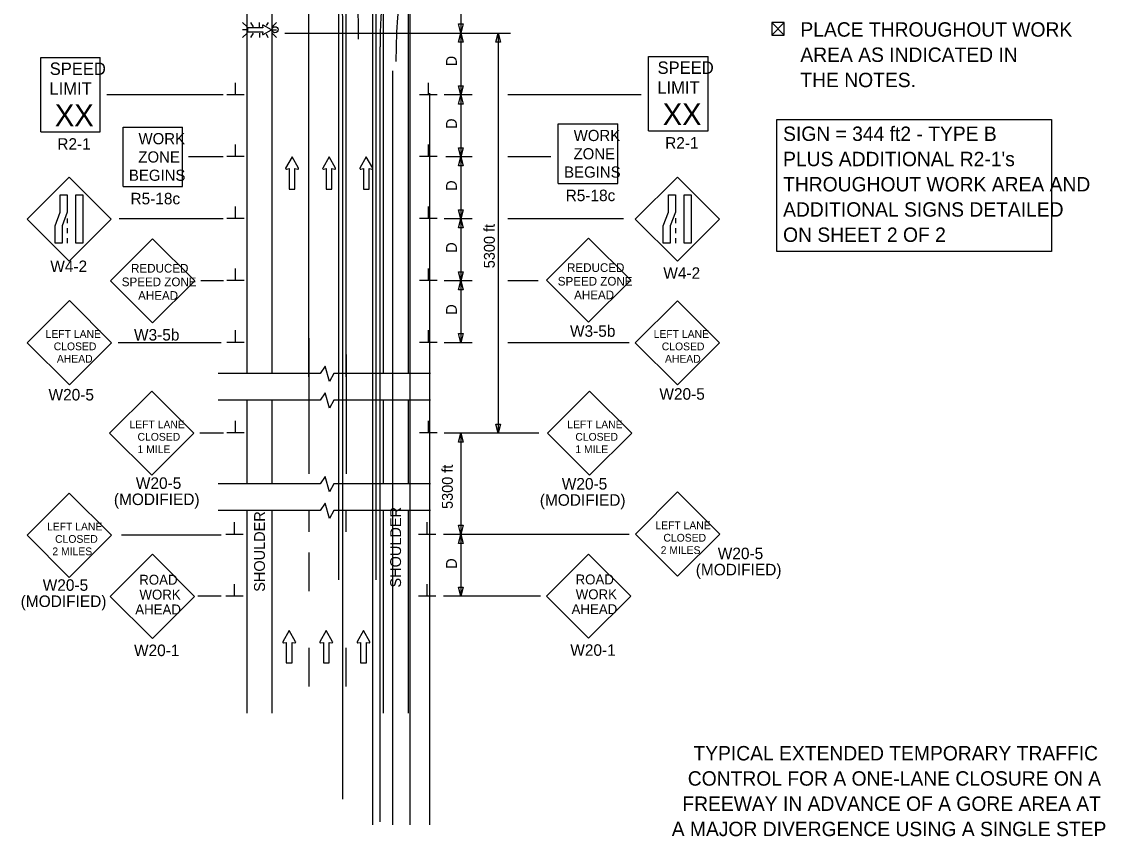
# Model space of a CAD drawing. Extents: x 16284 to 18468, y 5417 to 6974.
# Drawn here: x 16740 to 17439, y 5990 to 6516 of the extents above; entities that cross this region are included whole.
import ezdxf

# ---------------------------------------------------------------- set-up
doc = ezdxf.new("R2010")
doc.units = 0
for name, color, linetype in [('ALI_LEGAL_EX', 7, 'Continuous'), ('BORDER', 7, 'Continuous'), ('MT_SCRATCH_LEVEL_E', 7, 'Continuous'), ('PAVT_EDGE_EX', 7, 'Continuous'), ('TRAFFIC_SIGNS_PR', 7, 'Continuous'), ('TYPICAL_TEXT_DIMEN_EX', 7, 'Continuous'), ('TYPICAL_TEXT_DIMEN_PR', 7, 'Continuous')]:
    doc.layers.add(name, color=color, linetype=linetype)

msp = doc.modelspace()

# ---------------------------------------------------------------- linework, layer by layer
at = {"layer": 'ALI_LEGAL_EX'}
for p, q in [((16944.3, 6974.12), (16944.3, 6155.98)), ((16968.3, 6974.12), (16968.3, 6155.98)), ((16966.29, 6836.53), (16966.29, 5997.6)), ((16990.29, 6836.53), (16990.29, 5997.6)), ((16925.13, 6287.02), (16925.13, 6564.7)), ((16949.13, 6287.02), (16949.13, 6564.7)), ((16947.12, 6014.17), (16947.12, 6514.52)), ((16971.12, 5999.68), (16971.12, 6500.03)), ((16979.26, 5997.6), (16979.26, 6484.64)), ((17003.26, 5997.6), (17003.26, 6470.15)), ((16925.13, 6301.47), (16925.13, 6224.31)), ((16949.13, 6301.47), (16949.13, 6224.31))]:
    msp.add_line(p, q, dxfattribs=at)
for points in [[(16925.13, 6487.02), (16925.13, 6509.03)], [(16949.13, 6487.02), (16949.13, 6509.03)], [(16925.13, 6387.02), (16925.13, 6412.02)], [(16949.13, 6387.02), (16949.13, 6412.02)], [(16925.13, 6312.02), (16925.13, 6287.02)], [(16925.13, 6312.02), (16925.13, 6289.11)], [(16949.13, 6289.11), (16949.13, 6312.02)], [(16925.13, 6273.62), (16925.13, 6248.62)], [(16925.13, 6200.69), (16925.13, 6187.02)], [(16949.13, 6187.02), (16949.13, 6200.69)], [(16925.13, 6173.62), (16925.13, 6148.62)], [(16925.13, 6112.02), (16925.13, 6087.02)], [(16949.13, 6087.02), (16949.13, 6112.02)]]:
    msp.add_lwpolyline(points, dxfattribs=at)
for centre, radius, start, end in [((16583.12, 6514.52), 364, 0, 57.29578), ((16593.27, 6505.1), 364, 0, 57.29578), ((17311.12, 6500.03), 340, 129.56655, 180), ((17321.27, 6490.61), 340, 129.56655, 180)]:
    msp.add_arc(centre, radius, start, end, dxfattribs=at)
at = {"layer": 'MT_SCRATCH_LEVEL_E'}
for p, q in [((16914.27, 6429.09), (16910.15, 6421.85)), ((16918.41, 6421.85), (16914.27, 6429.09)), ((16938.17, 6429.09), (16934.06, 6421.85)), ((16942.32, 6421.85), (16938.17, 6429.09)), ((16962.22, 6429.09), (16958.11, 6421.85)), ((16966.37, 6421.85), (16962.22, 6429.09)), ((16910.64, 6421.16), (16912.41, 6421.48)), ((16912.41, 6421.48), (16912.41, 6408.22)), ((16916.16, 6408.22), (16916.16, 6421.48)), ((16916.16, 6421.48), (16917.93, 6421.16)), ((16934.54, 6421.16), (16936.32, 6421.48)), ((16936.32, 6421.48), (16936.32, 6408.22)), ((16940.06, 6408.22), (16940.06, 6421.48)), ((16940.06, 6421.48), (16941.84, 6421.16)), ((16958.59, 6421.16), (16960.37, 6421.48)), ((16960.37, 6421.48), (16960.37, 6408.22)), ((16964.11, 6408.22), (16964.11, 6421.48)), ((16964.11, 6421.48), (16965.89, 6421.16)), ((16912.41, 6408.22), (16916.16, 6408.22)), ((16936.32, 6408.22), (16940.06, 6408.22)), ((16960.37, 6408.22), (16964.11, 6408.22)), ((16912.44, 6123.16), (16908.32, 6115.92)), ((16916.58, 6115.92), (16912.44, 6123.16)), ((16936.34, 6123.16), (16932.23, 6115.92)), ((16940.49, 6115.92), (16936.34, 6123.16)), ((16960.39, 6123.16), (16956.28, 6115.92)), ((16964.54, 6115.92), (16960.39, 6123.16)), ((16908.81, 6115.24), (16910.58, 6115.55)), ((16910.58, 6115.55), (16910.58, 6102.29)), ((16914.33, 6102.29), (16914.33, 6115.55)), ((16914.33, 6115.55), (16916.1, 6115.24)), ((16932.71, 6115.24), (16934.49, 6115.55)), ((16934.49, 6115.55), (16934.49, 6102.29)), ((16938.23, 6102.29), (16938.23, 6115.55)), ((16938.23, 6115.55), (16940.01, 6115.24)), ((16956.76, 6115.24), (16958.54, 6115.55)), ((16958.54, 6115.55), (16958.54, 6102.29)), ((16962.28, 6102.29), (16962.28, 6115.55)), ((16962.28, 6115.55), (16964.06, 6115.24)), ((16910.58, 6102.29), (16914.33, 6102.29)), ((16934.49, 6102.29), (16938.23, 6102.29)), ((16958.54, 6102.29), (16962.28, 6102.29))]:
    msp.add_line(p, q, dxfattribs=at)
for centre, start, end in [((16910.56, 6421.62), 150.42484, 279.96381), ((16918, 6421.62), 260.03619, 29.77312), ((16934.47, 6421.62), 150.42484, 279.96381), ((16941.91, 6421.62), 260.03619, 29.77312), ((16958.52, 6421.62), 150.42484, 279.96381), ((16965.96, 6421.62), 260.03619, 29.77312), ((16908.73, 6115.69), 150.42484, 279.96381), ((16916.17, 6115.7), 260.03619, 29.77312), ((16932.64, 6115.69), 150.42484, 279.96381), ((16940.08, 6115.7), 260.03619, 29.77312), ((16956.69, 6115.69), 150.42484, 279.96381), ((16964.13, 6115.7), 260.03619, 29.77312)]:
    msp.add_arc(centre, 0.463, start, end, dxfattribs=at)
at = {"layer": 'PAVT_EDGE_EX'}
for p, q in [((16885.13, 6564.7), (16885.13, 6289.11)), ((16901.13, 6564.7), (16901.13, 6289.11)), ((16973.13, 6564.7), (16973.13, 6289.11)), ((16989.13, 6564.7), (16989.13, 6289.11)), ((16885.13, 6271.97), (16885.13, 6217.82)), ((16901.13, 6271.97), (16901.13, 6217.82)), ((16973.13, 6271.97), (16973.13, 6217.82)), ((16989.13, 6271.97), (16989.13, 6217.82)), ((16885.13, 6200.69), (16885.13, 6069.75)), ((16901.13, 6200.69), (16901.13, 6069.75)), ((16973.13, 6200.69), (16973.13, 6069.75)), ((16989.13, 6200.69), (16989.13, 6069.75))]:
    msp.add_line(p, q, dxfattribs=at)
at = {"layer": 'TRAFFIC_SIGNS_PR'}
for p, q in [((16885.2, 6513.11), (16882.38, 6515.93)), ((16887.5, 6515.93), (16889.13, 6513.11)), ((16893.29, 6513.11), (16893.29, 6515.93)), ((16898.76, 6515.93), (16897.55, 6513.83)), ((16904.19, 6515.92), (16901.37, 6513.11)), ((16885.2, 6511.07), (16882.38, 6511.07)), ((16885.2, 6509.04), (16882.38, 6506.22)), ((16889.15, 6509.04), (16887.52, 6506.22)), ((16893.29, 6509.04), (16893.29, 6506.22)), ((16897.47, 6508.41), (16898.73, 6506.22)), ((16901.37, 6511.07), (16904.19, 6511.07)), ((16904.19, 6506.22), (16901.37, 6509.04)), ((16752.07, 6493.12), (16790.47, 6493.12)), ((16752.07, 6445.12), (16752.07, 6493.12)), ((16790.47, 6445.12), (16790.47, 6493.12)), ((17144.45, 6493.8), (17182.85, 6493.8)), ((17144.45, 6445.8), (17144.45, 6493.8)), ((17182.85, 6445.8), (17182.85, 6493.8)), ((17086.09, 6411.89), (17086.09, 6450.29)), ((17086.09, 6450.29), (17124.49, 6450.29)), ((17124.49, 6411.89), (17124.49, 6450.29)), ((16752.07, 6445.12), (16790.47, 6445.12)), ((16805.17, 6409.84), (16805.17, 6448.24)), ((16805.17, 6448.24), (16843.57, 6448.24)), ((16843.57, 6409.84), (16843.57, 6448.24)), ((17144.45, 6445.8), (17182.85, 6445.8)), ((16770.39, 6416.02), (16743.23, 6388.86)), ((16797.54, 6388.86), (16770.39, 6416.02)), ((17163, 6416.04), (17135.85, 6388.89)), ((17190.15, 6388.89), (17163, 6416.04)), ((16805.17, 6409.84), (16843.57, 6409.84)), ((17086.09, 6411.89), (17124.49, 6411.89)), ((16743.23, 6388.86), (16770.39, 6361.71)), ((16769.14, 6389.36), (16769.14, 6386.16)), ((16770.39, 6361.71), (16797.54, 6388.86)), ((17135.85, 6388.89), (17163, 6361.73)), ((17161.75, 6389.38), (17161.75, 6386.18)), ((17163, 6361.73), (17190.15, 6388.89)), ((16769.14, 6382.96), (16769.14, 6379.76)), ((17161.75, 6382.98), (17161.75, 6379.78)), ((16769.14, 6376.56), (16769.14, 6373.36)), ((16824.3, 6376.18), (16797.15, 6349.03)), ((16851.45, 6349.03), (16824.3, 6376.18)), ((17105.74, 6376.58), (17078.59, 6349.43)), ((17132.9, 6349.43), (17105.74, 6376.58)), ((17161.75, 6376.58), (17161.75, 6373.38)), ((16797.15, 6349.03), (16824.3, 6321.88)), ((16824.3, 6321.88), (16851.45, 6349.03)), ((17078.59, 6349.43), (17105.74, 6322.27)), ((17105.74, 6322.27), (17132.9, 6349.43)), ((16770.51, 6336.22), (16743.32, 6309.03)), ((16797.7, 6309.03), (16770.51, 6336.22)), ((17163.03, 6336.19), (17135.84, 6309)), ((17190.22, 6309), (17163.03, 6336.19)), ((16743.32, 6309.03), (16770.51, 6281.85)), ((16770.51, 6281.85), (16797.7, 6309.03)), ((17135.84, 6309), (17163.03, 6281.81)), ((17163.03, 6281.81), (17190.22, 6309)), ((16823.71, 6277.82), (16796.52, 6250.64)), ((16850.9, 6250.64), (16823.71, 6277.82)), ((17106.33, 6277.81), (17079.14, 6250.62)), ((17133.51, 6250.62), (17106.33, 6277.81)), ((16796.52, 6250.64), (16823.71, 6223.45)), ((16823.71, 6223.45), (16850.9, 6250.64)), ((17079.14, 6250.62), (17106.33, 6223.43)), ((17106.33, 6223.43), (17133.51, 6250.62)), ((16770.49, 6211.86), (16743.31, 6184.67)), ((16797.68, 6184.67), (16770.49, 6211.86)), ((17163.18, 6212.64), (17136, 6185.45)), ((17190.37, 6185.45), (17163.18, 6212.64)), ((16743.31, 6184.67), (16770.49, 6157.49)), ((16770.49, 6157.49), (16797.68, 6184.67)), ((17136, 6185.45), (17163.18, 6158.27)), ((17163.18, 6158.27), (17190.37, 6185.45)), ((16824.1, 6172.41), (16796.94, 6145.26)), ((16851.25, 6145.26), (16824.1, 6172.41)), ((17105.74, 6172.59), (17078.59, 6145.44)), ((17132.9, 6145.44), (17105.74, 6172.59)), ((16796.94, 6145.26), (16824.1, 6118.11)), ((16824.1, 6118.11), (16851.25, 6145.26)), ((17078.59, 6145.44), (17105.74, 6118.28)), ((17105.74, 6118.28), (17132.9, 6145.44))]:
    msp.add_line(p, q, dxfattribs=at)
for points in [[(16895.11, 6513.76), (16895.34, 6512.46), (16885.62, 6512.46), (16885.62, 6509.72), (16895.34, 6509.72), (16895.11, 6508.41)], [(16895.61, 6508.06), (16900.92, 6511.07), (16895.61, 6514.11)]]:
    msp.add_lwpolyline(points, dxfattribs=at)
for points in [[(16769.14, 6404.6), (16769.14, 6393.42), (16765.8, 6384.54), (16765.8, 6373.36), (16761.3, 6373.36), (16761.3, 6384.54), (16764.65, 6393.42), (16764.65, 6404.6)], [(16779.28, 6404.6), (16779.28, 6373.36), (16774.78, 6373.36), (16774.78, 6404.6)], [(17161.75, 6404.62), (17161.75, 6393.44), (17158.41, 6384.56), (17158.41, 6373.38), (17153.91, 6373.38), (17153.91, 6384.56), (17157.26, 6393.44), (17157.26, 6404.62)], [(17171.89, 6404.62), (17171.89, 6373.38), (17167.4, 6373.38), (17167.4, 6404.62)]]:
    msp.add_lwpolyline(points, close=True, dxfattribs=at)
msp.add_circle((16903.24, 6511.12), 2, dxfattribs=at)
for centre, start, end in [((16895.45, 6513.81), 61.48329, 189.95933), ((16895.45, 6508.36), 170.73078, 298.89165)]:
    msp.add_arc(centre, 0.341, start, end, dxfattribs=at)
at = {"layer": 'TYPICAL_TEXT_DIMEN_EX'}
msp.add_lwpolyline([(17227.21, 6453.17), (17404.48, 6453.17), (17404.48, 6367.85), (17227.21, 6367.85)], close=True, dxfattribs=at)
at = {"layer": 'TYPICAL_TEXT_DIMEN_PR'}
for p, q in [((17023.24, 6541.14), (17023.24, 6509.03)), ((17023.24, 6509.03), (17021.67, 6514.9)), ((17021.67, 6514.9), (17023.24, 6514.9)), ((17023.24, 6514.9), (17024.81, 6514.9)), ((17024.81, 6514.9), (17023.24, 6509.03)), ((17224.01, 6515.74), (17232.01, 6507.74)), ((17224.01, 6507.74), (17232.01, 6515.74)), ((16909.53, 6509.03), (17055.35, 6509.03)), ((17021.67, 6503.17), (17023.24, 6509.03)), ((17023.24, 6509.03), (17023.24, 6469.03)), ((17023.24, 6509.03), (17024.81, 6503.17)), ((17045.77, 6503.17), (17047.34, 6509.03)), ((17047.34, 6509.03), (17047.34, 6250.63)), ((17047.34, 6509.03), (17048.91, 6503.17)), ((17023.24, 6503.17), (17021.67, 6503.17)), ((17024.81, 6503.17), (17023.24, 6503.17)), ((17047.34, 6503.17), (17045.77, 6503.17)), ((17048.91, 6503.17), (17047.34, 6503.17)), ((16877.81, 6469.12), (16877.81, 6476.9)), ((17002.26, 6469.12), (17002.26, 6476.9)), ((17023.24, 6469.03), (17021.67, 6474.9)), ((17021.67, 6474.9), (17023.24, 6474.9)), ((17023.24, 6474.9), (17024.81, 6474.9)), ((17024.81, 6474.9), (17023.24, 6469.03)), ((16869.89, 6469.03), (16794.8, 6469.03)), ((16883.43, 6469.12), (16872.18, 6469.12)), ((17007.88, 6469.12), (16996.63, 6469.12)), ((17030.45, 6469.03), (17012.41, 6469.03)), ((17021.67, 6463.17), (17023.24, 6469.03)), ((17023.24, 6469.03), (17023.24, 6429.03)), ((17023.24, 6469.03), (17024.81, 6463.17)), ((17139.57, 6469.03), (17053.57, 6469.03)), ((17023.24, 6463.17), (17021.67, 6463.17)), ((17024.81, 6463.17), (17023.24, 6463.17)), ((16877.69, 6429.28), (16877.69, 6437.06)), ((17002.26, 6429.28), (17002.26, 6437.06)), ((16869.89, 6429.03), (16847.44, 6429.03)), ((16883.32, 6429.28), (16872.07, 6429.28)), ((17007.88, 6429.28), (16996.63, 6429.28)), ((17030.45, 6429.03), (17013.53, 6429.03)), ((17023.24, 6429.03), (17021.67, 6434.9)), ((17021.67, 6434.9), (17023.24, 6434.9)), ((17021.67, 6423.17), (17023.24, 6429.03)), ((17023.24, 6434.9), (17024.81, 6434.9)), ((17024.81, 6434.9), (17023.24, 6429.03)), ((17023.24, 6429.03), (17023.24, 6389.03)), ((17023.24, 6429.03), (17024.81, 6423.17)), ((17081.26, 6429.03), (17053.57, 6429.03)), ((17023.24, 6423.17), (17021.67, 6423.17)), ((17024.81, 6423.17), (17023.24, 6423.17)), ((16877.69, 6389.28), (16877.69, 6397.06)), ((17002.26, 6389.28), (17002.26, 6397.06)), ((17023.24, 6389.03), (17021.67, 6394.9)), ((17021.67, 6394.9), (17023.24, 6394.9)), ((17023.24, 6394.9), (17024.81, 6394.9)), ((17024.81, 6394.9), (17023.24, 6389.03)), ((16869.89, 6389.03), (16802.62, 6389.03)), ((16883.32, 6389.28), (16872.07, 6389.28)), ((17007.88, 6389.28), (16996.63, 6389.28)), ((17030.45, 6389.03), (17012.41, 6389.03)), ((17021.67, 6383.17), (17023.24, 6389.03)), ((17023.24, 6389.03), (17023.24, 6349.03)), ((17023.24, 6389.03), (17024.81, 6383.17)), ((17128.19, 6389.03), (17053.57, 6389.03)), ((17023.24, 6383.17), (17021.67, 6383.17)), ((17024.81, 6383.17), (17023.24, 6383.17)), ((16877.69, 6349.28), (16877.69, 6357.06)), ((17002.26, 6349.28), (17002.26, 6357.06)), ((17023.24, 6349.03), (17021.67, 6354.9)), ((17021.67, 6354.9), (17023.24, 6354.9)), ((17023.24, 6354.9), (17024.81, 6354.9)), ((17024.81, 6354.9), (17023.24, 6349.03)), ((16869.99, 6349.03), (16855.42, 6349.03)), ((16883.32, 6349.28), (16872.07, 6349.28)), ((17007.88, 6349.28), (16996.63, 6349.28)), ((17030.45, 6349.03), (17012.41, 6349.03)), ((17021.67, 6343.17), (17023.24, 6349.03)), ((17023.24, 6349.03), (17023.24, 6309.03)), ((17023.24, 6349.03), (17024.81, 6343.17)), ((17073.15, 6349.03), (17053.57, 6349.03)), ((17023.24, 6343.17), (17021.67, 6343.17)), ((17024.81, 6343.17), (17023.24, 6343.17)), ((16877.69, 6309.28), (16877.69, 6317.06)), ((17002.26, 6309.28), (17002.26, 6317.06)), ((17023.24, 6309.03), (17021.67, 6314.9)), ((17021.67, 6314.9), (17023.24, 6314.9)), ((17023.24, 6314.9), (17024.81, 6314.9)), ((17024.81, 6314.9), (17023.24, 6309.03)), ((16868.54, 6309.03), (16801.99, 6309.03)), ((16883.32, 6309.28), (16872.07, 6309.28)), ((17007.88, 6309.28), (16996.63, 6309.28)), ((17030.45, 6309.03), (17012.41, 6309.03)), ((17131.79, 6309.03), (17053.57, 6309.03)), ((16932.48, 6289.11), (16866.54, 6289.11)), ((16935.74, 6293.91), (16932.48, 6289.11)), ((16938.48, 6283.97), (16935.74, 6293.91)), ((16941.22, 6289.11), (16938.48, 6283.97)), ((17003.55, 6289.11), (16941.22, 6289.11)), ((16935.74, 6276.77), (16932.48, 6271.97)), ((16938.48, 6266.83), (16935.74, 6276.77)), ((16932.48, 6271.97), (16866.54, 6271.97)), ((16941.22, 6271.97), (16938.48, 6266.83)), ((17003.55, 6271.97), (16941.22, 6271.97)), ((16877.69, 6250.88), (16877.69, 6258.66)), ((17002.26, 6250.88), (17002.26, 6258.66)), ((17047.34, 6250.63), (17045.77, 6256.5)), ((17045.77, 6256.5), (17047.34, 6256.5)), ((17047.34, 6256.5), (17048.91, 6256.5)), ((17048.91, 6256.5), (17047.34, 6250.63)), ((16870.03, 6250.63), (16854.78, 6250.63)), ((16883.32, 6250.88), (16872.07, 6250.88)), ((17007.88, 6250.88), (16996.63, 6250.88)), ((17073.63, 6250.63), (17012.41, 6250.63)), ((17021.67, 6244.77), (17023.24, 6250.63)), ((17023.24, 6250.63), (17023.24, 6185.29)), ((17023.24, 6250.63), (17024.81, 6244.77)), ((17023.24, 6244.77), (17021.67, 6244.77)), ((17024.81, 6244.77), (17023.24, 6244.77)), ((16935.74, 6222.62), (16932.48, 6217.82)), ((16938.48, 6212.69), (16935.74, 6222.62)), ((16932.48, 6217.82), (16866.54, 6217.82)), ((16941.22, 6217.82), (16938.48, 6212.69)), ((17003.55, 6217.82), (16941.22, 6217.82)), ((16935.74, 6205.49), (16932.48, 6200.69)), ((16938.48, 6195.55), (16935.74, 6205.49)), ((16932.48, 6200.69), (16866.54, 6200.69)), ((16941.22, 6200.69), (16938.48, 6195.55)), ((17003.55, 6200.69), (16941.22, 6200.69)), ((16877.14, 6185.29), (16877.14, 6193.08)), ((17001.51, 6185.29), (17001.51, 6193.08)), ((17023.24, 6185.29), (17021.67, 6191.16)), ((17021.67, 6191.16), (17023.24, 6191.16)), ((17023.24, 6191.16), (17024.81, 6191.16)), ((17024.81, 6191.16), (17023.24, 6185.29)), ((16868.54, 6184.67), (16804.08, 6184.67)), ((16882.76, 6185.29), (16871.51, 6185.29)), ((17007.13, 6185.29), (16995.88, 6185.29)), ((17131.79, 6185.29), (17012.13, 6185.29)), ((17021.67, 6179.43), (17023.24, 6185.29)), ((17023.24, 6185.29), (17023.24, 6145.29)), ((17023.24, 6185.29), (17024.81, 6179.43)), ((17023.24, 6179.43), (17021.67, 6179.43)), ((17024.81, 6179.43), (17023.24, 6179.43)), ((16877.14, 6145.29), (16877.14, 6153.08)), ((17001.51, 6145.29), (17001.51, 6153.08)), ((17023.24, 6145.29), (17021.67, 6151.16)), ((17021.67, 6151.16), (17023.24, 6151.16)), ((17023.24, 6151.16), (17024.81, 6151.16)), ((17024.81, 6151.16), (17023.24, 6145.29)), ((16868.54, 6145.29), (16853.39, 6145.29)), ((16882.76, 6145.29), (16871.51, 6145.29)), ((17007.13, 6145.29), (16995.88, 6145.29)), ((17074.69, 6145.29), (17012.13, 6145.29))]:
    msp.add_line(p, q, dxfattribs=at)
msp.add_lwpolyline([(17224.01, 6515.74), (17224.01, 6507.74), (17232.01, 6507.74), (17232.01, 6515.74)], close=True, dxfattribs=at)

# ---------------------------------------------------------------- texts
at = {"layer": 'BORDER'}
for s, p in [('TYPICAL EXTENDED TEMPORARY TRAFFIC', (17173.37, 6039.3)), ('CONTROL FOR A ONE-LANE CLOSURE ON A', (17169.74, 6023)), ('FREEWAY IN ADVANCE OF A GORE AREA AT', (17166.24, 6006.7)), ('A MAJOR DIVERGENCE USING A SINGLE STEP', (17159.37, 5990.4))]:
    msp.add_text(s, height=9.3, dxfattribs=at).set_placement(p)
at = {"layer": 'TRAFFIC_SIGNS_PR'}
for s, height, p in [('SPEED', 8, (16757.84, 6481.98)), ('SPEED', 8, (17150.22, 6482.67)), ('LIMIT', 8, (17150.06, 6469.87)), ('LIMIT', 8, (16757.68, 6469.18)), ('XX', 14.031, (16761.18, 6448.88)), ('XX', 14.031, (17153.56, 6449.56)), ('WORK', 7.217, (16815.17, 6437.21)), ('WORK', 7.217, (17096.09, 6439.26)), ('R2-1', 7.44, (16762.75, 6433.68)), ('R2-1', 7.44, (17155.13, 6434.36)), ('ZONE', 7.217, (16815.05, 6425.4)), ('ZONE', 7.217, (17095.97, 6427.45)), ('BEGINS', 7.217, (17089.9, 6415.64)), ('BEGINS', 7.217, (16808.98, 6413.59)), ('R5-18c', 7.44, (17090.9, 6400.45)), ('R5-18c', 7.44, (16809.98, 6398.4)), ('W4-2', 7.44, (16758.22, 6354.67)), ('REDUCED', 5.6, (16810.36, 6354.34)), ('REDUCED', 5.6, (17091.8, 6354.74)), ('W4-2', 7.44, (17153.96, 6350.3)), ('SPEED ZONE', 5.6, (16804.35, 6345.54)), ('SPEED ZONE', 5.6, (17085.8, 6345.94)), ('AHEAD', 5.6, (16814.91, 6336.74)), ('AHEAD', 5.6, (17096.35, 6337.14)), ('LEFT LANE', 5.006, (16755.19, 6312.19)), ('W3-5b', 7.44, (16812.26, 6310.44)), ('W3-5b', 7.44, (17093.7, 6312.86)), ('LEFT LANE', 5.006, (17147.71, 6312.16)), ('CLOSED', 5.006, (16760.43, 6304.19)), ('CLOSED', 5.006, (17152.95, 6304.15)), ('AHEAD', 5.006, (16762.48, 6296.18)), ('AHEAD', 5.006, (17155, 6296.14)), ('W20-5', 7.449, (16757.07, 6271.74)), ('W20-5', 7.449, (17151.4, 6272.23)), ('LEFT LANE', 5.006, (16809.32, 6253.79)), ('LEFT LANE', 5.006, (17091.94, 6253.78)), ('CLOSED', 5.006, (16814.54, 6245.78)), ('CLOSED', 5.006, (17097.15, 6245.77)), ('1 MILE', 5.006, (16814.53, 6237.78)), ('1 MILE', 5.006, (17097.15, 6237.76)), ('W20-5', 7.449, (16813.45, 6214.65)), ('W20-5', 7.449, (17088.41, 6214.21)), ('(MODIFIED)', 7.449, (16799.25, 6204.2)), ('(MODIFIED)', 7.449, (17074.22, 6203.75)), ('LEFT LANE', 5.006, (16756.1, 6187.83)), ('LEFT LANE', 5.006, (17148.8, 6188.61)), ('CLOSED', 5.006, (16761.32, 6179.82)), ('CLOSED', 5.006, (17154.01, 6180.6)), ('2 MILES', 5.006, (16759.57, 6171.81)), ('2 MILES', 5.006, (17152.26, 6172.59)), ('W20-5', 7.449, (17189.09, 6169.25)), ('(MODIFIED)', 7.449, (17174.89, 6158.8)), ('W20-5', 7.449, (16753.32, 6148.82)), ('ROAD', 6.4, (16815.64, 6152.79)), ('ROAD', 6.4, (17097.29, 6152.97)), ('WORK', 6.4, (16815.75, 6143.19)), ('WORK', 6.4, (17097.39, 6143.37)), ('(MODIFIED)', 7.449, (16739.12, 6138.37)), ('AHEAD', 6.4, (16813.06, 6133.59)), ('AHEAD', 6.4, (17094.7, 6133.77)), ('W20-1', 7.44, (16812.27, 6106.67)), ('W20-1', 7.44, (17093.91, 6106.84))]:
    msp.add_text(s, height=height, dxfattribs=at).set_placement(p)
at = {"layer": 'TYPICAL_TEXT_DIMEN_EX'}
for s, p in [('PLACE THROUGHOUT WORK', (17242.42, 6506.68)), ('AREA AS INDICATED IN', (17242.42, 6490.38)), ('THE NOTES.', (17242.42, 6474.08)), ('SIGN = 344 ft2 - TYPE B', (17231.26, 6439.34)), ("PLUS ADDITIONAL R2-1's", (17231.26, 6423.04)), ('THROUGHOUT WORK AREA AND', (17231.26, 6406.74)), ('ADDITIONAL SIGNS DETAILED', (17231.26, 6390.44)), ('ON SHEET 2 OF 2', (17231.26, 6374.14))]:
    msp.add_text(s, height=9.3, dxfattribs=at).set_placement(p)
at = {"layer": 'TYPICAL_TEXT_DIMEN_PR'}
for s, p in [('D', (17020.68, 6487.55)), ('D', (17020.68, 6447.12)), ('D', (17020.68, 6407.12)), ('5300 ft', (17045.14, 6357.12)), ('D', (17020.68, 6367.12)), ('D', (17020.68, 6327.12)), ('5300 ft', (17018.06, 6201.67)), ('SHOULDER', (16896.77, 6148.2)), ('SHOULDER', (16984.63, 6150.94)), ('D', (17020.68, 6163.04))]:
    msp.add_text(s, height=7, rotation=90, dxfattribs=at).set_placement(p)

doc.saveas('drawing.dxf')
